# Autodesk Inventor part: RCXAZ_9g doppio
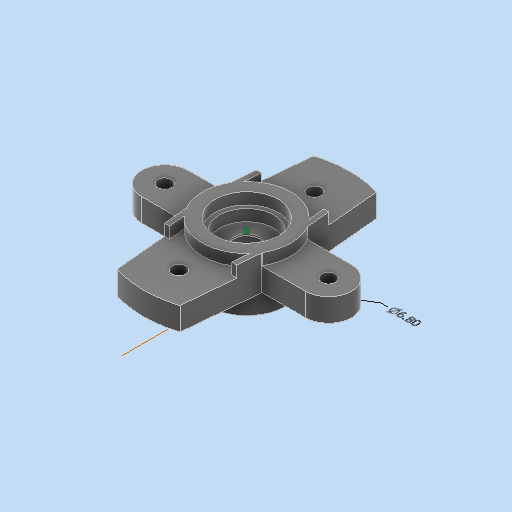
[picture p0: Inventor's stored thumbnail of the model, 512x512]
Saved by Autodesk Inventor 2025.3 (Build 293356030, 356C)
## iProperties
Created: 2026-03
Part Number: RCXAZ_9g doppio
Material: Generico
Document SubType Name: Modeling
Designer: R5800u
Density: 1 g/cm^3
Appearance: Liscia - Nero
Author: R5800u
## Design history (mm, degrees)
node "Annotazioni"
  node "Quota diametro 4" dims "d44" = 6.8 (derived)
sketch "Schizzo1"
  geometry: C1 r 3.4 at (0, 0); 1 further point
  constraints: 1 centre point, 1 coincident
  dimensions: "d0" = 6.8 diameter of C1
extrude "Estrusione1" new body sketch "Schizzo1" distance "d1" = 4; taper "d2" = 0 deg
sketch "Schizzo2" dims "d4" = 4
  geometry: L1 (0, 0)-(0, 15.5); L2 (-3.398, 0.127)-(-1.992, 15.68); L3 (0, 0)-(-8.473, 0); L4 (0, 0)-(0, -18); L5 (-3.398, -0.127)-(-3.398, 0.127); L6 (3.398, -0.127)-(3.398, 0.127); L7 (3.398, 0.127)-(1.992, 15.68); L8 (-3.386, -0.307)-(-1.767, -18.16); L9 (3.476, 0.685)-(1.767, -18.16); C1 r 3.4 at (0, 0); A1 r 3.4 centre (0, 0) between (-3.398, -0.127) and (-3.398, 0.127) reference; A2 r 1.774 centre (0, -18) between (-1.767, -18.16) and (1.767, -18.16); 11 further points
  constraints: 18 end point, 4 point on circle, 3 coincident, 3 symmetric about line, 3 tangent, 2 centre point, 2 vertical, 1 horizontal, 7 other
  dimensions: "d3" = 15.5 distance of L1.start L1.end; "d57" = 18 distance of L1.start L4.end
extrude "Estrusione2" join sketch "Schizzo2" distance "d5" = 2; taper "d6" = 0 deg
sketch "Schizzo3"
  geometry: C1 r 2.75 at (0, 0); A1 r 3.4 centre (0, 0) between (3.365, 0.485) and (-3.365, 0.485) reference; A2 r 3.4 centre (0, 0) between (3.365, 0.485) and (-3.365, 0.485) reference; A3 r 3.4 centre (0, 0) between (-3.365, 0.485) and (3.365, 0.485); 10 further points
  constraints: 2 centre point, 2 coincident, 1 point on circle
  dimensions: "d7" = 5.5 diameter of C1
extrude "Estrusione3" join sketch "Schizzo3" distance "d8" = 0.01; taper "d9" = 0 deg
sketch "Schizzo5"
  geometry: C1 r 2.75 at (0, 0) reference; 2 further points
  constraints: 1 coincident
hole "Foro1" sketch "Schizzo5" at (0, 0) diameter "d10" = 2.2; stored, may be unused: countersink angle "d14" = 90 deg, drill point angle "d16" = 118 deg; dims "d11" = 6, "d12" = 4.75, "d13" = 1, "d15" = 8
sketch "Schizzo6"
  geometry: C1 r 2.5 at (0, 0); 1 further point
  constraints: 1 centre point, 1 coincident
  dimensions: "d17" = 5 diameter of C1
extrude "Estrusione4" cut sketch "Schizzo6" distance "d18" = 2.85; taper "d19" = 0 deg
sketch "Schizzo7"
  geometry: L1 (-3.386, -0.309)-(-2, -15.5) reference; L2 (1.992, -15.681)-(3.386, -0.307) reference; A1 r 3.4 centre (0, 0) between (-3.386, -0.309) and (3.386, -0.307) reference; A2 r 2 centre (0, -15.5) between (-2, -15.5) and (1.992, -15.681) reference; 2 further points
  constraints: 1 coincident
hole "Foro2" sketch "Schizzo7" at (0, -15.5) diameter "d20" = 1.2; stored, may be unused: countersink angle "d24" = 90 deg, drill point angle "d26" = 118 deg; dims "d21" = 6, "d22" = 4.4, "d23" = 2.3, "d25" = 8
pattern_linear "Serie rettangolare1" dims "d29" = 2.4
mirror "Speculare1"
sketch "Schizzo8"
  geometry: 1 further point
sketch "Schizzo9"
  geometry: C1 r 2.375 at (0, 0) reference; C2 r 8.868 at (0, 0); C3 r 1.1 at (0, 0) reference; C4 r 25.415 at (0, 0); 1 further point
  constraints: 2 centre point, 2 coincident
extrude "Estrusione5" cut sketch "Schizzo9" extent not by distance; stored distance "d32" = 0; taper "d33" = 0 deg
sketch "Schizzo10"
  geometry: L1 (0, 0)-(9, 0); L2 (0.028, 1.9)-(9.028, 1.9); L3 (9.028, 1.9)-(9.028, -1.9); L4 (9.028, -1.9)-(0.028, -1.9); L5 (0.028, -1.9)-(0.028, 1.9); C1 r 3.4 at (0, 0) reference; 2 further points
  constraints: 10 end point, 2 horizontal, 2 parallel, 1 perpendicular, 1 other
  dimensions: "d46" = 3.8 distance of L2.end L3.end; "d69" = 9 distance of L3.end L4.end
extrude "Estrusione6" join sketch "Schizzo10" stored distance "d47" = 4; taper "d48" = 0 deg
fillet "Raccordo1" dims "d49" = 1.9
sketch "Schizzo11"
  geometry: A1 r 1.9 centre (7.128, 0) between (7.128, -1.9) and (7.128, 1.9) reference; 2 further points
  constraints: 1 coincident
hole "Foro3" sketch "Schizzo11" at (7.128, 0) diameter "d50" = 1.2; stored, may be unused: countersink angle "d54" = 90 deg, drill point angle "d56" = 118 deg; dims "d51" = 6, "d52" = 4, "d53" = 2, "d55" = 8
mirror "Speculare2"
sketch "Schizzo12"
  geometry: 1 further point
sketch "Schizzo13"
  geometry: L1 (-7.128, 1.9)-(-3.237, 1.9) reference; L2 (-3.242, -1.9)-(-7.128, -1.9) reference; L3 (-3.242, -1.9)-(-2.646, -8.464) reference; L4 (2.646, -8.464)-(3.242, -1.9) reference; L5 (3.242, -1.9)-(7.128, -1.9) reference; L6 (7.128, 1.9)-(3.237, 1.9) reference; L7 (3.237, 1.9)-(2.644, 8.465) reference; L8 (-2.644, 8.465)-(-3.237, 1.9) reference; L9 (-7.128, 2)-(-3.329, 2); L10 (-3.329, 2)-(-2.738, 8.54); L11 (2.738, 8.54)-(3.329, 2); L12 (3.329, 2)-(7.128, 2); L13 (7.128, -2)-(3.333, -2); L14 (3.333, -2)-(2.74, -8.539); L15 (-2.74, -8.539)-(-3.333, -2); L16 (-3.333, -2)-(-7.128, -2); L17 (3.945, -4.75)-(-3.945, -4.75); L18 (-3.945, -4.75)-(-3.945, 4.75); L19 (-3.945, 4.75)-(3.945, 4.75); L20 (3.945, 4.75)-(3.945, -4.75); L21 (3.945, -4.75)-(-3.945, 4.75); L22 (-3.945, -4.75)-(3.945, 4.75); C1 r 3.85 at (0, 0); C2 r 3.4 at (0, 0) reference; C3 r 0.6 at (-7.128, 0) reference; C4 r 0.6 at (0, 5.9) reference; C5 r 0.6 at (0, -5.9) reference; C6 r 0.6 at (7.128, 0) reference; A1 r 1.1 centre (0, 0) between (-1.1, 0) and (1.1, 0) reference; A2 r 0.6 centre (0, 8.3) between (-0.2, 8.866) and (0.2, 8.866) reference; A3 r 0.6 centre (0, -8.3) between (0.2, -8.866) and (-0.2, -8.866) reference; A4 r 1.9 centre (-7.128, 0) between (-7.128, 1.9) and (-7.128, -1.9) reference; A5 r 8.868 centre (0, 0) between (-2.646, -8.464) and (-0.2, -8.866) reference; A6 r 1.9 centre (7.128, 0) between (7.128, -1.9) and (7.128, 1.9) reference; A7 r 8.868 centre (0, 0) between (0.2, -8.866) and (2.646, -8.464) reference; A8 r 2 centre (-7.128, 0) between (-7.128, 2) and (-7.128, -2); A9 r 8.968 centre (0, 0) between (2.738, 8.54) and (-2.738, 8.54); A10 r 2 centre (7.128, 0) between (7.128, -2) and (7.128, 2); A11 r 8.968 centre (0, 0) between (-2.74, -8.539) and (2.74, -8.539); A12 r 2.75 centre (0, 0) between (-2.75, 0) and (2.75, 0) reference; A13 r 2.75 centre (0, 0) between (2.75, 0) and (-2.75, 0) reference; A14 r 8.868 centre (0, 0) between (2.644, 8.465) and (0.2, 8.866) reference; A15 r 8.868 centre (0, 0) between (-0.2, 8.866) and (-2.644, 8.465) reference; 16 further points
  constraints: 28 end point, 8 point on circle, 5 centre point, 2 coincident, 2 midpoint, 2 parallel, 1 horizontal, 1 horizontal alignment, 1 perpendicular, 13 other
  dimensions: "d58" = 7.7 diameter of C1; "d59" = 0.1 radial gap between concentric circles of A4 A8; "d64" = 9.5 distance of L17.end L18.end
  node "Linea chiusa proiettata2"
extrude "Estrusione7" join sketch "Schizzo13" stored distance "d60" = 10; taper "d61" = 0 deg
extrude "Estrusione8" join sketch "Schizzo13" distance "d62" = 1; taper "d63" = 0 deg
sketch "Schizzo14"
  geometry: L1 (-7.128, -2)-(-3.333, -2) reference; L2 (-3.333, -2)-(-2.74, -8.539) reference; L3 (2.74, -8.539)-(3.333, -2) reference; L4 (3.333, -2)-(7.128, -2) reference; L5 (7.128, 2)-(3.329, 2) reference; L6 (3.329, 2)-(2.738, 8.54) reference; L7 (-2.738, 8.54)-(-3.329, 2) reference; L8 (-3.329, 2)-(-7.128, 2) reference; L9 (-2.335, -8.21)-(-2.938, -1.567); L10 (-2.938, -1.567)-(-7.128, -1.567); L11 (-7.128, 1.567)-(-2.933, 1.567); L12 (-2.933, 1.567)-(-2.333, 8.21); L13 (2.333, 8.21)-(2.933, 1.567); L14 (2.933, 1.567)-(7.128, 1.567); L15 (7.128, -1.567)-(2.938, -1.567); L16 (2.938, -1.567)-(2.335, -8.21); L17 (-3.152, -4)-(3.152, -4); L18 (-3.148, 4)-(3.148, 4); L19 (-3.329, 2)-(-3.329, 1.934); L20 (-3.333, -2)-(-3.333, -1.927); L21 (3.333, -2)-(3.333, -1.927); L22 (3.329, 2)-(3.333, 1.927); C1 r 0.6 at (-7.128, 0) reference; C2 r 0.6 at (0, 5.9) reference; C3 r 0.6 at (0, -5.9) reference; C4 r 0.6 at (7.128, 0) reference; A1 r 3.85 centre (0, 0) between (-3.329, 1.934) and (-3.333, -1.927) reference; A2 r 2 centre (-7.128, 0) between (-7.128, 2) and (-7.128, -2) reference; A3 r 8.968 centre (0, 0) between (-2.74, -8.539) and (2.74, -8.539) reference; A4 r 2 centre (7.128, 0) between (7.128, -2) and (7.128, 2) reference; A5 r 8.968 centre (0, 0) between (2.738, 8.54) and (-2.738, 8.54) reference; A6 r 1.567 centre (-7.128, 0) between (-7.128, 1.567) and (-7.128, -1.567); A7 r 8.535 centre (0, 0) between (2.333, 8.21) and (-2.333, 8.21); A8 r 1.567 centre (7.128, 0) between (7.128, -1.567) and (7.128, 1.567); A9 r 8.535 centre (0, 0) between (-2.335, -8.21) and (2.335, -8.21); 9 further points
  constraints: 28 end point, 12 point on circle, 5 point on line, 4 centre point, 2 parallel, 2 vertical, 1 horizontal, 11 other
  dimensions: "d65" = 4 distance from line of point (0, 0) L18; "d66" = 4 distance from line of point (0, 0) L17
extrude "Estrusione9" join sketch "Schizzo14" stored distance "d67" = 0.4; taper "d68" = 0 deg
node "Solido1"
node "Linea chiusa proiettata1"
node "Linea chiusa proiettata3"
other parameters: "d43" = 57.41156 (derived)
